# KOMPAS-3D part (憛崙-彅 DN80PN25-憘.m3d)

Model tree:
1. Объединить компоненты:1  (labels: СЕНС-ПФ DN80PN25)
2. Эскиз:1
3. Операция выдавливания:1
     Расстояние 1 = 14
4. Фаска:1
     Угол = 45; Длина 1 = 2; Длина 2 = 2

Referenced files in D:\Савин\!СЕНСОР\3D для заказчика\!Новый перечень\СЕНС-ПФ\DN80\: СЕНС-ПФ DN80PN25.a3d
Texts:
  СЕНС-ПФ DN80PN25-СВ
  ООО НПП Сенсор
  СЕНС-ПФ DN80PN25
